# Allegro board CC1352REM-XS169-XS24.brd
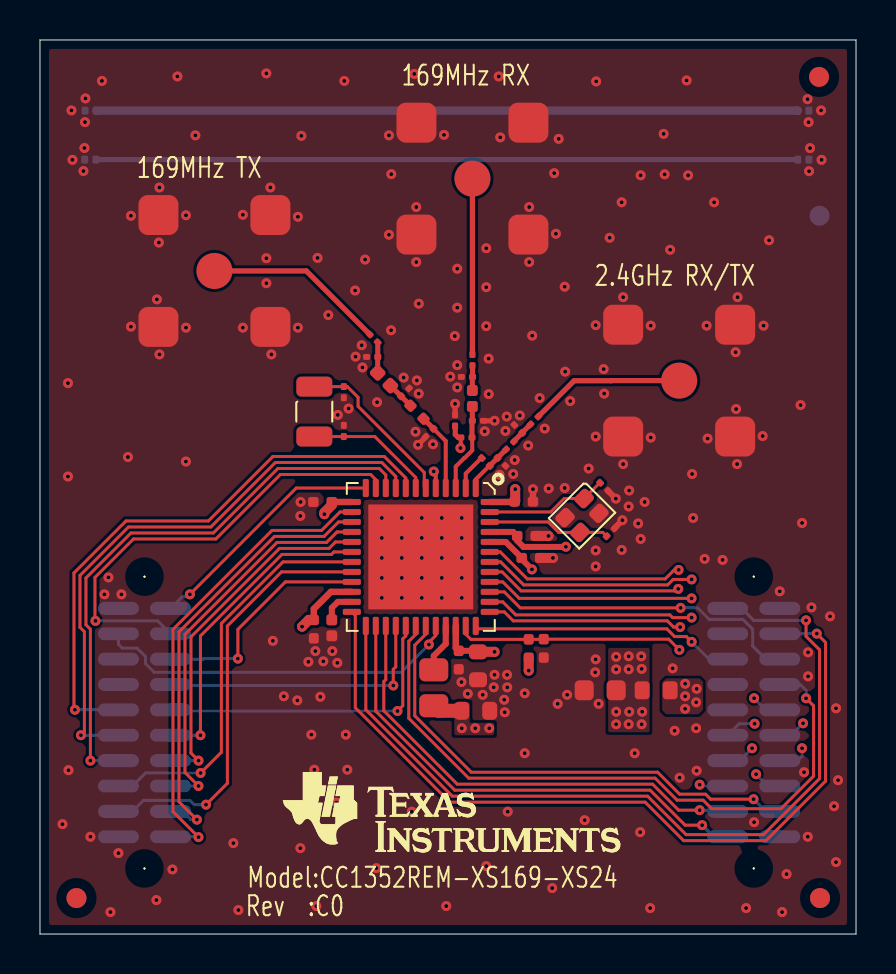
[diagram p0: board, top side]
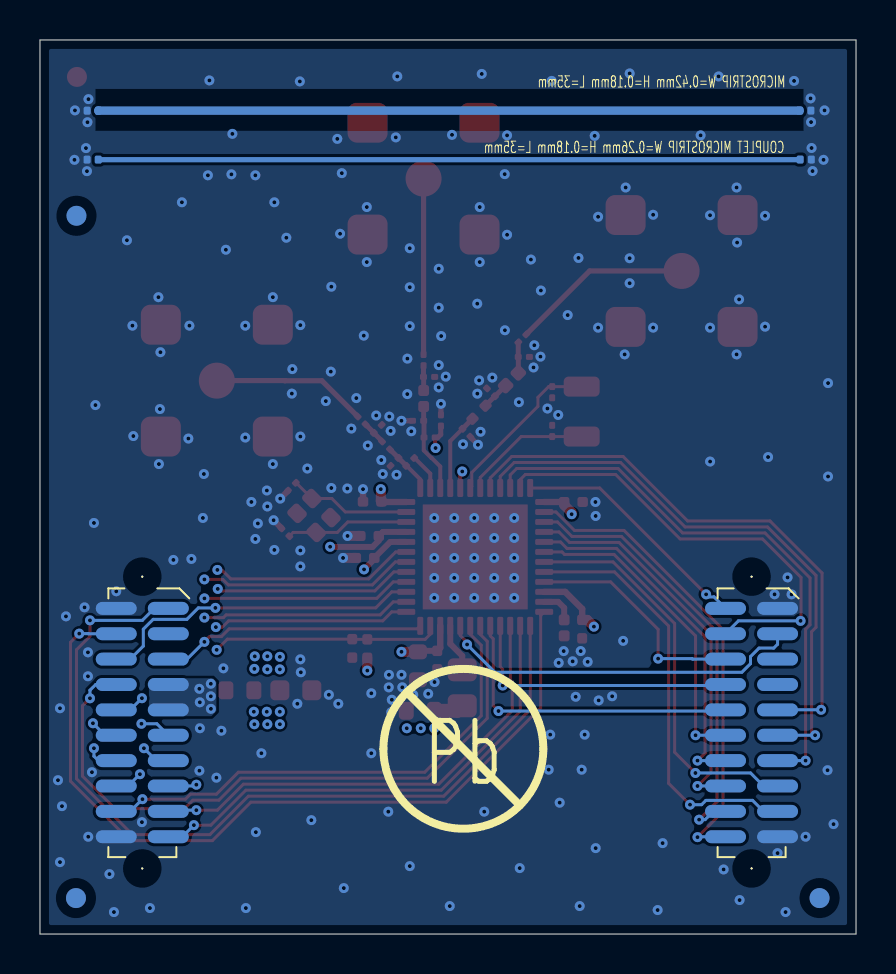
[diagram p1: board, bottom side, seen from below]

Outline 40.83 x 44.75 mm; copper layers: TOP, L2, L3, BOTTOM. Coordinates in mm from the lower left corner of the outline.
Outline path: 0,44.75 0,0 40.83,0 40.83,44.75 0,44.75

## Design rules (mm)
constraint set DEFAULT: min track width 0.15

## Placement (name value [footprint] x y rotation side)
C1  DNM  [CAPC1608X90A2N]  28.83 12.2 180 top
C11  1.5pF  [CAPC0603X35B2N]  22.89 23.83 315 top
C12  1.5pF  [CAPC0603X35B2N]  24.13 25.08 135 top
C15  12pF  [CAPC0603X35B2N]  24.54 25.51 45 top
C31  18pF  [CAPC0603X35B2N]  19.29 24.89 45 top
C32  33pF  [CAPC0603X35B2N]  18.07 26.92 45 top
C33  12pF  [CAPC0603X35B2N]  16.34 28.88 0 top
C36  680pF  [CAPC0603X35B2N]  16.89 29.62 135 top
C81  12pF  [CAPC0603X35B2N]  15.2 27.4 270 top
C91  12pF  [CAPC0603X35B2N]  15.2 24.9 90 top
C131  0.1uF  [CAPC1005X60B2N]  14.6 21.62 180 top
C221  0.1uF  [CAPC1005X60B2N]  13.7 15.72 270 top
C231  1uF  [CAPC1005X60A2N]  14.6 15.72 270 top
C331  22uF  [CAPC1608X100A2N]  21.1 11.17 0 top
C341  22uF  [CAPC1608X100A2N]  21.91 14.13 270 top
C342  0.1uF  [CAPC1005X60B2N]  20.95 14.17 270 top
C351  0.1uF  [CAPC1005X60B2N]  25.2 14.76 270 top
C441  0.1uF  [CAPC1005X60B2N]  24.1 18.83 0 top
C451  0.1uF  [CAPC1005X60B2N]  23.87 19.92 0 top
C461  8.2pF  [CAPC0603X35B2N]  28.35 19.91 45 top
C471  8.2pF  [CAPC0603X35B2N]  28.03 22.59 315 top
C481  0.1uF  [CAPC1005X60B2N]  23.74 21.64 0 top
C503  680pF  [CAPC0603X35B2N]  20.77 25.98 270 top
C504  680pF  [CAPC0603X35B2N]  21.63 29 270 top
C505  18pF  [CAPC0603X35B2N]  22.19 25.69 180 top
C506  12pF  [CAPC0603X35B2N]  21.08 27.88 0 top
FIDU1  FIDU_1MM  [FID100X115B]  1.83 1.8 0 top
FIDU2  FIDU_1MM  [FID100X115B]  39.02 1.8 0 top
FIDU3  FIDU_1MM  [FID100X115B]  38.98 42.9 0 top
FIDU4  FIDU_1MM  [FID100X115B]  1.83 1.8 180 bottom
FIDU5  FIDU_1MM  [FID100X115B]  39.02 1.8 180 bottom
FIDU6  FIDU_1MM  [FID100X115B]  39 35.95 180 bottom
FL1  BLM18HE152SN1  [FIL_BLM18HE152SN1DN]  30.12 12.2 0 top
J1  SMA-10V21-TGG  [HUSTSAN_SMA10V21TGGAN]  8.73 33.19 270 top
J2  SMA-10V21-TGG  [HUSTSAN_SMA10V21TGGAN]  31.98 27.7 0 top
J3  SMA-10V21-TGG  [HUSTSAN_SMA10V21TGGAN]  21.63 37.81 0 top
L11  15nH  [INDC0603X33A2N]  22.5 23.43 135 top
L12  2.8nH  [INDC0603X33A2N]  23.32 24.26 45 top
L31  150nH  [INDC0603X33A2N]  21.61 24.85 180 top
L32  47nH  [INDC1005X60B2N]  19.19 25.79 135 top
L33  68nH  [INDC1005X60A2N]  17.53 27.45 135 top
L331  6.8uH  [INDC2012X150A2N]  19.7 13.22 270 top
L338  82nH  [INDC1005X60A2N#2]  21.63 26.41 90 top
LBL1  NON_COMPONENT_LABEL_8mm  [LABEL_PB-FREE_8MM_A2N]  23.86 5.06 180 bottom
LBL2  TI_LOGO  [TI_LOGO_1]  13.15 8.11 0 top
NOREF  -  []  -59.15 -73.28 0 top
NOREF#2  -  []  0 43.78 0 top
NOREF#3  -  []  39.33 0 90 top
P1  SFM-110-02-S-D-A-K  [SAMTEC_SFM11002AN]  3.92 16.3 0 bottom
P2  SFM-110-02-S-D-A-K  [SAMTEC_SFM11002AN]  34.4 16.3 0 bottom
R351  100k  [RESC1005X40B2N]  24.45 14.75 270 top
R352  0  [RESC0603X35B2N]  38.46 41.21 180 bottom
R353  0  [RESC0603X35B2N]  2.25 41.21 0 bottom
R354  0  [RESC0603X35B2N]  2.23 38.77 0 bottom
R355  0  [RESC0603X35B2N]  38.47 38.76 180 bottom
U1  CC1352R1F3RGZ  [QFNFC50P700X700X100-49A2N]  21.8 22.33 180 top
Y1  32.768kHz  [XTAL_FC135_A2N]  13.72 27.4 270 top
Y2  48MHz  [OSCCC200X160X50-4B2N]  27.22 21.8 225 top

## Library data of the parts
C1 = CAPACITOR: User Part Number: #PN; alternate symbols: (CAPC1608X90A2L,CAPC1608X90A2M)
C11 C12 C15 C31-C33 C36 C81 C91 C461 C471 C503-C506 = CAPACITOR: User Part Number: #PN; alternate symbols: (CAPC0603X35B2L,CAPC0603X35B2M)
C131 C221 C342 C351 C441 C451 C481 = CAPACITOR: User Part Number: #PN
C231 = CAPACITOR: User Part Number: #PN; alternate symbols: (CAPC1005X60A2L,CAPC1005X60A2M)
C331 C341 = CAPACITOR: User Part Number: #PN; alternate symbols: (CAPC1608X100A2L,CAPC1608X100A2M)
FIDU1-FIDU6 = FIDMARK
FL1 = FILTER_2PIN: alternate symbols: (FIL_BLM18HE152SN1DL,FIL_BLM18HE152SN1DM)
J1-J3 = CONN_COAX_1+4: alternate symbols: (HUSTSAN_SMA10V21TGGL,HUSTSAN_SMA10V21TGGM)
L11 L12 L31 = INDUCTOR: User Part Number: #PN; alternate symbols: (INDC0603X33A2L,INDC0603X33A2M)
L32 = INDUCTOR: User Part Number: #PN
L33 L338 = INDUCTOR: User Part Number: #PN; alternate symbols: (INDC1005X60A2L,INDC1005X60A2M)
L331 = INDUCTOR: User Part Number: #PN; alternate symbols: (INDC2012X150A2L,INDC2012X150A2M)
LBL1 = LABEL_Pb-free_V1: User Part Number: #PN
LBL2 = TI_LOGO_V1
P1 P2 = CONN_HEADER_2X10_P_S: alternate symbols: (SAMTEC_SFM11002AL,SAMTEC_SFM11002AM)
R351 = RESISTOR: User Part Number: #PN
R352-R355 = RESISTOR: User Part Number: #PN; alternate symbols: (RESC0603X35B2L,RESC0603X35B2M)
U1 = IC_RF_CC1352R_VQFN48: User Part Number: #PN; alternate symbols: (QFNFC50P700X700X100-49A2L,QFNFC50P700X700X100-49A2M)
Y1 = CRYSTAL: User Part Number: #PN; alternate symbols: (XTAL_FC135_A2L,XTAL_FC135_A2M)
Y2 = XTAL_4PINS_1_3: User Part Number: #PN; alternate symbols: (OSCCC200X160X50-4B2L,OSCCC200X160X50-4B2M)

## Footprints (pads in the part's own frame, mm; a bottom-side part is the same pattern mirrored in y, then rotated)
CAPC0603X35B2N
  custom 0.075x0.075 smd: 1(0,0) 2(0.56,0)
CAPC1005X60A2N
  custom 0.135x0.135 smd: 1(0,0) 2(0.8,0)
CAPC1005X60B2N
  custom 0.125x0.125 smd: 1(0,0) 2(0.924,0)
CAPC1608X90A2N
  custom 0.237x0.237 smd: 1(0,0) 2(1.6,0)
CAPC1608X100A2N
  custom 0.188x0.188 smd: 1(0,0) 2(1.4,0)
FID100X115B
  round 1 smd: 1(0,0)
FIL_BLM18HE152SN1DN
  custom 0.188x0.188 smd: 1(0,0) 2(1.4,0)
HUSTSAN_SMA10V21TGGAN
  round 1.801 smd: 1(0,0)
  custom 0.5x0.5 smd: 2(-2.8,-2.8) 3(2.8,-2.8) 4(2.8,2.8) 5(-2.8,2.8)
INDC0603X33A2N
  custom 0.075x0.075 smd: 1(0,0) 2(0.56,0)
INDC1005X60A2N
  custom 0.16x0.16 smd: 1(0,0) 2(0.9,0)
INDC1005X60A2N#2
  custom 0.135x0.135 smd: 1(0,0) 2(0.8,0)
INDC1005X60B2N
  custom 0.125x0.125 smd: 1(0,0) 2(0.924,0)
INDC2012X150A2N
  custom 0.287x0.287 smd: 1(0,0) 2(1.8,0)
OSCCC200X160X50-4B2N
  custom 0.188x0.188 smd: 1(0,0) 2(1.35,0) 3(1.35,1.05) 4(0,1.05)
QFNFC50P700X700X100-49A2N
  custom 0.075x0.075 smd: 1(0,0) 2(0.5,0) 3(1,0) 4(1.5,0) 5(2,0) 6(2.5,0) 7(3,0) 8(3.5,0) 9(4,0) 10(4.5,0) 11(5,0) 12(5.5,0) 13(6.2,0.7) 14(6.2,1.2) 15(6.2,1.7) 16(6.2,2.2) 17(6.2,2.7) 18(6.2,3.2) 19(6.2,3.7) 20(6.2,4.2) 21(6.2,4.7) 22(6.2,5.2) 23(6.2,5.7) 24(6.2,6.2) 25(5.5,6.9) 26(5,6.9) 27(4.5,6.9) 28(4,6.9) 29(3.5,6.9) 30(3,6.9) 31(2.5,6.9) 32(2,6.9) 33(1.5,6.9) 34(1,6.9) 35(0.5,6.9) 36(0,6.9) 37(-0.7,6.2) 38(-0.7,5.7) 39(-0.7,5.2) 40(-0.7,4.7) 41(-0.7,4.2) 42(-0.7,3.7) 43(-0.7,3.2) 44(-0.7,2.7) 45(-0.7,2.2) 46(-0.7,1.7) 47(-0.7,1.2) 48(-0.7,0.7)
  rect 5.25x5.25 smd: 49(2.75,3.45)
RESC0603X35B2N
  custom 0.087x0.087 smd: 1(0,0) 2(0.56,0)
RESC1005X40B2N
  custom 0.125x0.125 smd: 1(0,0) 2(0.924,0)
SAMTEC_SFM11002AN
  round 0.099 hole 1.501 unplated: (1.302,-1.588) (1.302,13.017)
  oval 2.05x0.65 smd: 1(0,0) 2(2.604,0) 3(0,1.27) 4(2.604,1.27) 5(0,2.54) 6(2.604,2.54) 7(0,3.81) 8(2.604,3.81) 9(0,5.08) 10(2.604,5.08) 11(0,6.35) 12(2.604,6.35) 13(0,7.62) 14(2.604,7.62) 15(0,8.89) 16(2.604,8.89) 17(0,10.16) 18(2.604,10.16) 19(0,11.43) 20(2.604,11.43)
XTAL_FC135_A2N
  custom 0.25x0.25 smd: 1(0,0) 2(2.5,0)

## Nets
GND: C1.2 C11.2 C12.2 C31.1 C32.2 C33.1 C81.2 C91.2 C131.2 C221.2 C231.2 C331.2 C341.2 C342.2 C351.2 C441.2 C451.2 C461.2 C471.2 C481.2 C503.1 C505.1 C506.1 J1.2 J1.3 J1.4 J1.5 J2.2 J2.3 J2.4 J2.5 J3.2 J3.3 J3.4 J3.5 P1.1 P1.19 P2.2 P2.20 R352.1 R353.1 R354.1 R355.1 U1.49 Y2.2 Y2.4(GND#4)
VDD_EB: FL1.2 P2.7 P2.9
VDDR: C331.1 C451.1 C481.1 L331.2 U1.45 U1.48
VDDS: C1.1 C131.1 C221.1 C341.1 C342.1 C441.1 FL1.1 R351.2 U1.13 U1.22 U1.34 U1.44
DCDC_SW: L331.1 U1.33
DIO_3: P1.9 U1.8
DIO_4: P1.11 U1.9
DIO_5: P1.13 U1.10
DIO_6: P1.4 U1.11
DIO_7: P1.2 U1.12
DIO_8: P1.20 U1.14
DIO_9: P1.18 U1.15(DIO_9)
DIO_10: P1.16 U1.16
DIO_11: P1.14 U1.17
DIO_12: P1.12 U1.18
DIO_13: P1.15 U1.19
DIO_14: P1.17 U1.20
DIO_15: P1.6 U1.21
DIO_16 / JTAG TDO: P2.19 U1.26
DIO_17 / JTAG TDI: P2.17 U1.27
DIO_18: P1.8 U1.28
DIO_19: P1.10 U1.29
DIO_20: P2.8 U1.30
DIO_21: P2.18 U1.31
DIO_22: P1.3 U1.32
DIO_23: P2.5 U1.36
DIO_24: P2.10 U1.37
DIO_25: P2.11 U1.38
DIO_26: P2.6 U1.39
DIO_27: P2.13 U1.40
DIO_28: P2.16 U1.41
DIO_29: P2.14 U1.42
DIO_30: P2.12 U1.43
JTAG_TCK: P2.1 U1.25
JTAG_TMS: P2.4 U1.24
NRESET: C351.1 P2.15 R351.1 U1.35
RX_TX: C503.2 L31.2 U1.5
N485533: C36.2 J1.1
N485707: C91.1 U1.7 Y1.2
N501979: C461.1 U1.46 Y2.3
N512564: C15.2 J2.1
N567744: L11.2 U1.2
N567770: C11.1 L11.1 L12.1 U1.1
N3412703: C505.2 L31.1 L338.1 U1.3
N3413556: C31.2 L32.1 U1.4
N3413564: C32.1 L32.2 L33.1
N3413576: C33.2 C36.1 L33.2
N3415261: C504.1 J3.1
N3415578: C12.1 C15.1 L12.2
N3417420: C504.2 C506.2 L338.2
N3424378: C471.1 U1.47 Y2.1
N3424914: C231.1 U1.23
N3425185: C81.1 U1.6 Y1.1
N3440275: R352.2 R353.2
N3440401: R354.2 R355.2

Pads without a net: FIDU1 1; FIDU2 1; FIDU3 1; FIDU4 1; FIDU5 1; FIDU6 1; P1 5 7; P2 3

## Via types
v1: diameter 0.5, hole 0.2, TOP to BOTTOM, 314 vias

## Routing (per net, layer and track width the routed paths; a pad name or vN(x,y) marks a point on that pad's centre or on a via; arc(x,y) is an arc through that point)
GND: length 4.7
  TOP w0.26: C503.1 v1(20.77,26.54) ; v1(18.91,24.49) 19.29,24.87 C31.1 ; C505.1 v1(22.74,25.69)
  TOP w0.3: 28.75,20.31 28.75,20.32 v1(29.14,20.71) ; v1(28.81,21.79) 28.42,22.18 C471.2
  TOP w0.32: C481.2 v1(24.66,22.27)
  TOP w0.5: C451.2 v1(25.44,19.92) ; C441.2 v1(25.66,18.83)
  vias: v1(1.12,5.5) v1(1.4,27.58) v1(1.4,22.9) v1(1.42,8.2) v1(1.58,41.23) v1(1.62,38.75) v1(2.17,38.19) v1(2.27,41.83) v1(2.25,40.64) v1(2.22,39.34) v1(2.52,4.87) v1(3.1,42.7) v1(3.22,17) v1(3.42,17.85) v1(3.52,1.1) v1(3.92,4.05) v1(4.08,17) v1(4.4,23.88) v1(4.55,35.95) v1(4.55,30.4) v1(5.85,31.77) v1(5.83,1.7) v1(5.97,37.36) v1(5.95,34.61) v1(5.97,29.01) v1(6.62,3.23) v1(6.88,42.92) v1(7.3,35.98) v1(7.3,30.35) v1(7.3,23.65) v1(7.77,39.98) v1(9.67,4.55) v1(9.92,1.2) v1(10.15,36) v1(10.15,30.35) v1(11.33,43.08) v1(11.33,33.83) v1(11.33,32.58) v1(11.52,37.36) v1(11.58,29.01) v1(11.65,14.67) v1(12.2,11.9) v1(12.9,35.9) v1(12.9,30.35) v1(12.88,11.69) v1(13.04,21.62) v1(13.02,20.92) v1(13.02,4.3) v1(13.08,39.95) v1(13.42,13.62) v1(13.58,9.98) v1(13.77,14.16) v1(13.72,8.23) v1(13.83,1.4) v1(13.88,33.84) v1(14.02,11.88) v1(14.17,13.65) v1(14.42,30.98) v1(14.62,14.16) v1(14.83,6.58) v1(14.9,25.98) v1(14.88,13.58) v1(15.22,42.7) v1(15.3,9.98) v1(15.44,26.3) v1(15.38,8.23) v1(15.77,32.21) v1(15.79,28.9) v1(16.09,29.47) v1(16.13,28.36) v1(16.27,33.76) v1(16.86,26.62) v1(16.83,3.3) v1(17.1,20.83) v1(17.1,19.83) v1(17.1,18.83) v1(17.1,17.83) v1(17.1,16.83) v1(17.46,39.98) v1(17.46,35) v1(17.56,30.22) v1(17.58,38.03) v1(18.1,20.83) v1(18.1,19.83) v1(18.1,18.83) v1(18.1,17.83) v1(18.1,16.83) v1(18.19,27.85) v1(18.6,6.12) v1(18.72,43.05) v1(18.83,36.39) v1(18.83,33.63) v1(18.86,27.71) v1(18.78,25.14) v1(18.95,31.55) v1(18.95,27.05) v1(19.1,20.83) v1(19.1,19.83) v1(19.1,18.83) v1(19.1,17.83) v1(19.1,16.83) v1(19.66,24.51) v1(20.1,20.83) v1(20.1,19.83) v1(20.1,18.83) v1(20.1,17.83) v1(20.1,16.83) v1(20.21,40) v1(20.33,1.4) v1(20.52,27.9) v1(20.75,29.93) v1(20.88,33.3) v1(20.88,31.35) v1(20.88,28.47) v1(20.88,27.36) v1(21.1,20.83) v1(21.1,19.83) v1(21.1,18.83) v1(21.1,17.83) v1(21.1,16.83) v1(21.09,12.61) v1(21.4,12.02) v1(22.15,11.97) v1(22.25,25.16) v1(22.33,34.33) v1(22.33,32.38) v1(22.33,30.42) v1(22.33,3.4) v1(22.45,28.8) v1(22.45,27.02) v1(22.74,12.98) v1(22.7,12.35) v1(22.95,42.92) v1(23.02,39.87) v1(22.99,22.99) v1(23.22,11.73) v1(23.25,11.1) v1(23.35,25.9) v1(23.28,25.18) v1(23.37,12.97) v1(23.38,12.35) v1(23.4,6.12) v1(23.75,23.72) v1(23.67,23.02) v1(24,25.95) v1(24.25,12.05) v1(24.25,9.05) v1(24.42,24.45) v1(24.48,36.39) v1(24.48,33.63) v1(24.62,29.95) v1(25,26.83) v1(25.25,25.3) v1(25.45,22.3) v1(25.62,2.3) v1(25.73,38.08) v1(25.81,35.05) v1(25.95,39.8) v1(25.9,11.52) v1(26.25,32.4) v1(26.27,28.15) v1(26.25,22.33) v1(26.37,11.97) v1(26.52,26.67) v1(27.25,5.7) v1(27.45,23.3) v1(27.77,13.1) v1(27.83,42.67) v1(27.8,30.47) v1(27.8,24.9) v1(27.8,19.2) v1(27.8,18.4) v1(27.8,13.75) v1(27.95,11.52) v1(28.2,28.27) v1(28.23,27.05) v1(28.5,34.85) v1(29.1,36.62) v1(29.17,31.88) v1(29.17,23.52) v1(29.1,19.22) v1(29.45,21.4) v1(29.48,22.2) v1(29.75,9.05) v1(29.92,20.55) v1(30.05,37.98) v1(30.05,19.77) v1(30.02,5.1) v1(30.25,21.62) v1(30.55,30.45) v1(30.55,24.85) v1(30.52,1.3) v1(31.2,40.05) v1(31.25,38.02) v1(31.52,34.25) v1(31.65,13.3) v1(31.75,10.17) v1(32,7.83) v1(32.35,42.73) v1(32.42,37.98) v1(32.62,23.02) v1(32.67,20.83) v1(32.83,10.3) v1(32.85,8.17) v1(33.25,18.77) v1(33.35,30.45) v1(33.4,24.8) v1(33.73,36.62) v1(34.15,18.72) v1(34.8,29.12) v1(34.83,26.28) v1(34.87,23.52) v1(34.9,31.88) v1(35.33,1.3) v1(35.73,5.6) v1(36.15,24.92) v1(36.2,30.45) v1(36.48,34.73) v1(37.01,17.15) v1(37.12,1.1) v1(37.35,3) v1(38.05,26.47) v1(38.12,20.58) v1(38.23,8.1) v1(38.4,41.79) v1(38.45,40.63) v1(38.42,14.1) v1(38.42,12.9) v1(38.41,4.87) v1(38.52,39.34) v1(38.48,38.18) v1(38.59,16.35) v1(39.08,41.23) v1(39.1,38.75) v1(39.52,15.9) v1(39.73,6.4) v1(39.83,11.3) v1(39.83,3.6) v1(39.92,7.7)
VDD_EB:
  vias: v1(32.27,11.27) v1(32.28,12.53) v1(32.28,11.9) v1(32.85,12.27) v1(32.83,11.6)
VDDR: length 7.7
  TOP w0.3: v1(26.31,19.38) 26.3,19.38 24.19,19.38 23.87,19.69 C451.1 23.67,20.12 U1.45
  TOP w0.32: C481.1 23.73,21.62 U1.48
  TOP w0.5: C481.1 23.77,21.67 v1(23.77,22.27)
  TOP w0.7: L331.2 19.95,11.17 C331.1
  vias: v1(21.1,10.3) v1(21.77,10.3) v1(22.48,10.3)
VDDS: length 11.8
  TOP w0.3: C341.1 21.86,14.17 C342.1 ; U1.44 23.3,19.62 C441.1 24.1,18.76 v1(24.61,18.25)
  TOP w0.32: C221.1 13.7,16.27 14.55,17.12 U1.22 ; C342.1 20.8,14.33 U1.34 ; U1.13 C131.1
  TOP w0.5: C131.1 14.6,21.47 14.23,21.1 v1(14.23,21.01) ; C341.1 v1(22.74,14.13) ; v1(13.11,15.39) 13.45,15.72 C221.1 ; R351.2 v1(24.45,13.19)
  vias: v1(28.83,13.88) v1(28.83,13.25) v1(28.83,11.13) v1(28.82,10.5) v1(29.45,13.9) v1(29.45,13.25) v1(29.45,10.5) v1(29.48,11.13) v1(30.08,13.9) v1(30.1,13.27) v1(30.13,11.13) v1(30.1,10.5)
DCDC_SW: length 2.4
  TOP w0.3: L331.1 19.7,13.92 20.3,14.52 U1.33
DIO_3: length 29
  TOP w0.15: U1.8 18.3,22.83 17.23,23.9 11.65,23.9 8.42,20.67 4.3,20.67 1.7,18.07 1.7,11.27 v1(1.75,11.22)
  BOTTOM w0.15: v1(1.75,11.22) 3.92,11.22 P1.9
DIO_4: length 29
  TOP w0.15: U1.9 17.8,22.9 17.1,23.6 11.77,23.6 8.55,20.38 4.43,20.38 2,17.95 2,15.35 2.22,15.13 2.22,10.12 v1(2.05,9.95)
  BOTTOM w0.15: v1(2.05,9.95) P1.11
DIO_5: length 28.7
  TOP w0.15: U1.10 17.3,22.98 16.98,23.3 11.9,23.3 8.67,20.08 4.55,20.08 2.3,17.82 2.3,15.48 2.52,15.25 v1(2.52,8.68)
  BOTTOM w0.15: P1.13 v1(2.52,8.68)
DIO_6: length 22.9
  TOP w0.15: v1(2.77,15.67) 2.75,15.7 2.75,17.85 4.68,19.77 8.8,19.77 12.02,23 16.54,23 16.8,22.74 U1.11
  BOTTOM w0.15: P1.4 5.88,15.67 v1(2.77,15.67)
DIO_7: length 12.3
  TOP w0.15: U1.12 12.82,22.33 v1(7.5,17)
  BOTTOM w0.15: v1(7.5,17) 7.37,16.88 7.1,16.88 P1.2
DIO_8: length 23.7
  TOP w0.15: U1.14 15.01,21.12 14.08,20.2 11.61,20.2 6.65,15.25 6.65,6.13 v1(7.93,4.85)
  BOTTOM w0.15: P1.20 7.78,4.87 7.8,4.85 v1(7.93,4.85)
DIO_9: length 22.2
  TOP w0.15: v1(7.85,5.72) 6.95,6.62 6.95,15.12 11.73,19.9 14.21,19.9 14.94,20.62 U1.15
  BOTTOM w0.15: v1(7.85,5.72) 7.55,5.72 7.13,6.14 P1.18
DIO_10: length 19.7
  TOP w0.15: U1.16 14.86,20.12 14.33,19.6 11.86,19.6 7.25,15 7.25,8.09 v1(7.93,7.41)
  BOTTOM w0.15: v1(7.93,7.41) P1.16
DIO_11: length 17.8
  TOP w0.15: v1(7.93,8.68) 7.55,9.06 7.55,14.87 11.98,19.3 14.46,19.3 14.78,19.62 U1.17
  BOTTOM w0.15: v1(7.93,8.68) P1.14
DIO_12: length 15.8
  TOP w0.15: U1.18 14.71,19.12 14.58,19 12.11,19 8.03,14.92 v1(8.03,9.95)
  BOTTOM w0.15: v1(8.03,9.95) P1.12
DIO_13: length 20.1
  TOP w0.15: v1(8.04,8.06) 9.08,9.1 9.08,15.54 12.16,18.62 U1.19
  BOTTOM w0.15: v1(8.04,8.06) 5.28,8.06 4.62,7.41 P1.15
DIO_14: length 21.4
  TOP w0.15: v1(8.31,6.47) 9.38,7.54 9.38,15.42 12.08,18.12 U1.20
  BOTTOM w0.15: P1.17 4.62,6.14 5.17,6.69 7.51,6.69 7.72,6.47 v1(8.31,6.47)
DIO_15: length 11.5
  TOP w0.15: v1(9.9,13.78) 9.9,15.25 12.28,17.62 U1.21
  BOTTOM w0.15: v1(9.9,13.78) 8.2,13.78 8.17,13.76 P1.6
DIO_16 / JTAG TDO: length 24.5
  TOP w0.15: U1.26 16.8,11.15 20.75,7.2 30.52,7.2 32.27,5.45 v1(33.12,5.45)
  BOTTOM w0.15: P2.19 33.7,4.87 v1(33.12,5.45)
DIO_17 / JTAG TDI: length 23.6
  TOP w0.15: v1(33,6.2) 31.95,6.2 30.65,7.5 20.88,7.5 17.2,11.18 17.2,12.64 17.3,12.74 U1.27
  BOTTOM w0.15: P2.17 33.7,6.14 33.64,6.2 v1(33,6.2)
DIO_18: length 14.2
  TOP w0.15: v1(17.67,12.44) 17.67,13.25 17.8,13.38 U1.28
  BOTTOM w0.15: v1(17.67,12.44) 6.58,12.44 P1.8
DIO_19: length 15.8
  TOP w0.15: U1.29 18.3,14.92 18.15,14.77 18.15,11.42 v1(17.89,11.16)
  BOTTOM w0.15: P1.10 6.59,11.16 v1(17.89,11.16)
DIO_20: length 33.5
  TOP w0.15: U1.30 18.8,15 18.45,14.65 18.45,10.8 21.45,7.8 30.77,7.8 31.87,6.7 33.17,6.7 33.6,6.27 37.07,6.27 38.7,7.9 38.7,11.42 v1(38.33,11.8)
  BOTTOM w0.15: P2.8 38.04,12.49 38.33,12.2 v1(38.33,11.8)
DIO_21: length 25
  TOP w0.15: U1.31 19.3,15.01 18.75,14.46 18.75,10.92 21.58,8.1 30.9,8.1 32,7 33.3,7 33.55,6.75 v1(35.7,6.75)
  BOTTOM w0.15: v1(35.7,6.75) 36.31,6.14 P2.18
DIO_22: length 18.5
  TOP w0.15: v1(19.46,14.49) 19.46,14.6 19.8,14.94 U1.32
  BOTTOM w0.15: P1.3 3.92,14.5 4.12,14.31 4.85,14.31 5.28,13.88 5.28,13.53 5.71,13.1 18.07,13.1 v1(19.46,14.49)
DIO_23: length 13.3
  TOP w0.15: U1.36 21.95,15.27 31.36,15.27 31.75,14.89 32.34,14.89 v1(32.6,14.62)
  BOTTOM w0.15: P2.5 33.46,13.76 v1(32.6,14.62)
DIO_24: length 16.8
  TOP w0.15: v1(32.02,15.36) 31.7,15.36 31.39,15.67 23.68,15.67 23.23,16.12 U1.37
  L3 w0.15: v1(35.73,11.8) 35.2,12.33 35.2,12.7 32.53,15.36 v1(32.02,15.36)
  BOTTOM w0.15: v1(35.73,11.8) 36.31,11.22 P2.10
DIO_25: length 19
  TOP w0.15: U1.38 23.15,16.62 23.8,15.97 31.51,15.97 31.65,15.84 v1(32.6,15.84)
  L3 w0.15: v1(35.75,10.52) 36.2,10.97 36.2,12.24 v1(32.6,15.84)
  BOTTOM w0.15: P2.11 34.98,10.52 v1(35.75,10.52)
DIO_26: length 16.4
  TOP w0.15: v1(32.05,16.33) 24.03,16.33 23.23,17.12 U1.39
  BOTTOM w0.15: v1(32.05,16.33) 32.9,16.33 33.48,15.75 35.16,15.75 35.65,15.26 35.65,14.41 36.31,13.76 P2.6
DIO_27: length 21.4
  TOP w0.15: U1.40 23.15,17.62 23.98,16.8 v1(32.6,16.8)
  L3 w0.15: v1(32.6,16.8) 36.5,12.9 36.5,10.17 v1(35.62,9.3)
  BOTTOM w0.15: v1(35.62,9.3) 35.01,8.68 P2.13
DIO_28: length 23.5
  TOP w0.15: v1(31.93,17.27) 31.83,17.17 24.07,17.17 23.12,18.12 U1.41
  L3 w0.15: v1(35.83,8) 36.8,8.97 36.8,13.27 32.8,17.27 v1(31.93,17.27)
  BOTTOM w0.15: P2.16 37,7.4 36.42,7.4 v1(35.83,8)
DIO_29: length 23.1
  TOP w0.15: U1.42 23.05,18.62 24.2,17.47 31.4,17.47 31.68,17.75 v1(32.6,17.75)
  L3 w0.15: v1(38.12,9.3) 37.48,9.95 37.48,13.02 32.74,17.75 v1(32.6,17.75)
  BOTTOM w0.15: v1(38.12,9.3) 38.12,8.9 37.9,8.68 P2.14
DIO_30: length 22.4
  TOP w0.15: v1(31.95,18.22) 31.73,18.22 31.28,17.77 24.38,17.77 23.03,19.12 U1.43
  L3 w0.15: v1(31.95,18.22) 32.8,18.22 37.77,13.25 37.77,10.95 v1(38.17,10.55)
  BOTTOM w0.15: P2.12 37.58,9.95 v1(38.17,10.55)
JTAG_TCK: length 43
  TOP w0.15: U1.25 16.3,11.23 20.63,6.9 30.4,6.9 32.33,4.97 36.2,4.97 39,7.78 39,14.22 38.33,14.9 v1(38.33,15.7)
  BOTTOM w0.15: v1(38.33,15.7) 35.7,15.7 35.11,16.3 P2.1
JTAG_TMS: length 41.8
  TOP w0.15: U1.24 15.77,15.95 15.77,11.33 20.5,6.6 30.27,6.6 32.2,4.67 36.32,4.67 39.3,7.65 39.3,14.6 v1(38.86,15.04)
  BOTTOM w0.15: P2.4 38.4,15.03 38.41,15.04 v1(38.86,15.04)
NRESET: length 20.3
  TOP w0.15: U1.35 21.3,15.01 21.56,14.75 R351.1 25.19,14.75 C351.1 31.45,14.76 v1(31.99,14.22)
  L3 w0.15: v1(33,7.47) 33.33,7.8 33.33,12.88 v1(31.99,14.22)
  BOTTOM w0.15: v1(33,7.47) 33.07,7.41 P2.15
RX_TX: length 4
  TOP w0.2: v1(19.7,23.15) 19.7,23.1 19.8,23 U1.5 ; v1(21.03,24.33) 21.05,24.34 L31.2
  TOP w0.25: C503.2 20.77,25.42 20.77,25 20.92,24.85 L31.2
  L3 w0.32: v1(19.7,23.15) 20.87,24.33 v1(21.03,24.33)
N485533: length 9.1
  TOP w0.26: J1.1 13.32,33.19 16.5,30.01
N485707: length 6.4
  TOP w0.15: Y1.2 C91.1 16.75,24.9 18.8,22.85 U1.7
N501979: length 6.1
  TOP w0.15: U1.46 25.42,20.62 25.95,20.1 Y2.3 28.16,20.1 C461.1
N512564: length 7.8
  TOP w0.26: J2.1 28.57,27.7 28.57,27.69 26.72,27.69 C15.2
N567744: length 1.9
  TOP w0.2: L11.2 22.08,23.83 21.3,23.05 U1.2
N567770: length 2.6
  TOP w0.2: U1.1 21.8,22.75 22.48,23.43 L11.1
  TOP w0.25: L11.1 22.5,23.44 C11.1 22.89,23.83 L12.1
N3412703: length 4.4
  TOP w0.2: L31.1 21.62,24.84 21.62,24.21 21.24,23.83 21.23,23.83 20.8,23.4 U1.3 ; 21.61,25.67 C505.2
  TOP w0.25: L31.1 21.61,25.67 ; L338.1 C505.2
N3413556: length 3.9
  TOP w0.2: C31.2 20.3,24.68 U1.4
  TOP w0.25: L32.1 19.69,25.29 C31.2
N3413564: length 1.4
  TOP w0.25: L33.1 18.06,26.92 C32.1 18.53,26.45 L32.2
N3413576: length 1.5
  TOP w0.25: C36.1 16.9,29.61 C33.2 16.89,28.88 L33.2
N3415261: length 8.8
  TOP w0.26: C504.1 J3.1
N3415578: length 1.2
  TOP w0.25: 23.71,24.65 23.71,24.67 C12.1 24.13,25.1 C15.1
N3417420: length 1.2
  TOP w0.25: L338.2 21.63,27.88 C506.2 21.64,28.44 C504.2
N3424378: length 6.1
  TOP w0.15: C471.1 28.01,22.59 Y2.1 26.22,21.8 25.55,21.12 U1.47
N3424914: length 1.7
  TOP w0.3: U1.23 14.9,16.62 14.6,16.33 C231.1
N3425185: length 8.4
  TOP w0.15: U1.6 19.22,22.4 19.22,23.1 15.91,26.41 15.91,26.86 15.38,27.4 C81.1 Y1.1
N3440275: length 35.1
  BOTTOM w0.42: R352.2 37.9,41.21 R353.2
N3440401: length 35.1
  BOTTOM w0.26: R354.2 2.8,38.76 R355.2

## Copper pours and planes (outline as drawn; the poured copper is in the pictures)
GND on TOP: 0.45,44.3 0.45,0.45 40.37,0.45 40.37,44.3 ; 6 cut-outs
GND on BOTTOM: 0.45,44.3 0.45,0.45 40.37,0.45 40.37,44.3 ; 7 cut-outs
GND on L2: 0.45,44.3 0.45,0.45 40.37,0.45 40.37,44.3
GND on L3: 0.45,44.3 0.45,0.45 40.37,0.45 40.37,44.3 ; 1 cut-out
VDD_EB on TOP: 31.33,12.8 33,12.8 33.17,12.62 33.17,11.22 32.95,11 31.33,11 31.12,11.2 31.12,12.6
VDD_EB on BOTTOM: 32.17,12.8 35.12,12.8 35.37,12.55 35.37,11.15 35.12,10.9 32.25,10.9 32,11.15 32,12.62
VDDR on TOP: 20.72,11.6 21.5,11.6 21.5,10.58 22.73,10.58 22.73,9.95 20.72,9.95
VDDR on L3: 23.52,10.7 26.02,13.02 26.02,20.77 23.48,20.77 23.48,22.65 24.25,22.65 24.25,21.88 27.23,21.88 27.23,13.4 25.05,11.22 23.36,9.55 20.83,9.55 20.83,10.7
VDDS on TOP: 28.42,14.33 28.42,10.1 30.5,10.1 30.5,14.33
VDDS on L3: 17.2,7 15.72,8.58 15.72,14.45 15.3,14.95 12.83,14.95 12.83,15.6 13.15,15.85 15.3,15.85 15.72,16.55 15.72,20.2 13.6,20.2 13.6,21.33 16.52,21.33 16.52,9.12 17.17,8.52 19.58,8.52 19.58,15.27 24.1,15.27 24.1,18.62 25.05,18.62 25.05,12.88 24.1,12.88 24.1,13.8 20.67,13.8 20.67,9.42 28.4,9.42 28.42,14.45 30.6,14.45 30.6,6.92

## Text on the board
Ref Des/Silkscreen Bottom: MICROSTRIP W=0.42mm H=0.18mm L=35mm | COUPLET MICROSTRIP W=0.26mm H=0.18mm L=35mm
Ref Des/Silkscreen Top: 169MHz TX | Rev  :C0 | Model:CC1352REM-XS169-XS24 | 169MHz RX | 2.4GHz RX/TX
XSECTION_CHART: *  SURFACE - AIR 0 MM | L1 TOP CONDUCTOR - COPPER 0.035 MM | *  DIELECTRIC - 2116PV170 0.122 MM | *  DIELECTRIC - 106PV170 0.048 MM | L2 L2 PLANE - COPPER 0.017 MM | *  DIELECTRIC - FR-4 1.14 MM | L3 L3 PLANE - COPPER 0.017 MM | L4 BOTTOM CONDUCTOR - COPPER 0.035 MM | DESIGN CROSS SECTION CHART | ___________________________ | TOTAL THICKNESS 1.59 MM +/- 0.16 MM after press
DIMENSION: FIGURE | FINISHED_SIZE | 0.2 | 1.501 | DRILL CHART: TOP to BOTTOM | ALL UNITS ARE IN MILLIMETERS | PLATED | NON-PLATED | QTY | 289 | 25 | 4
